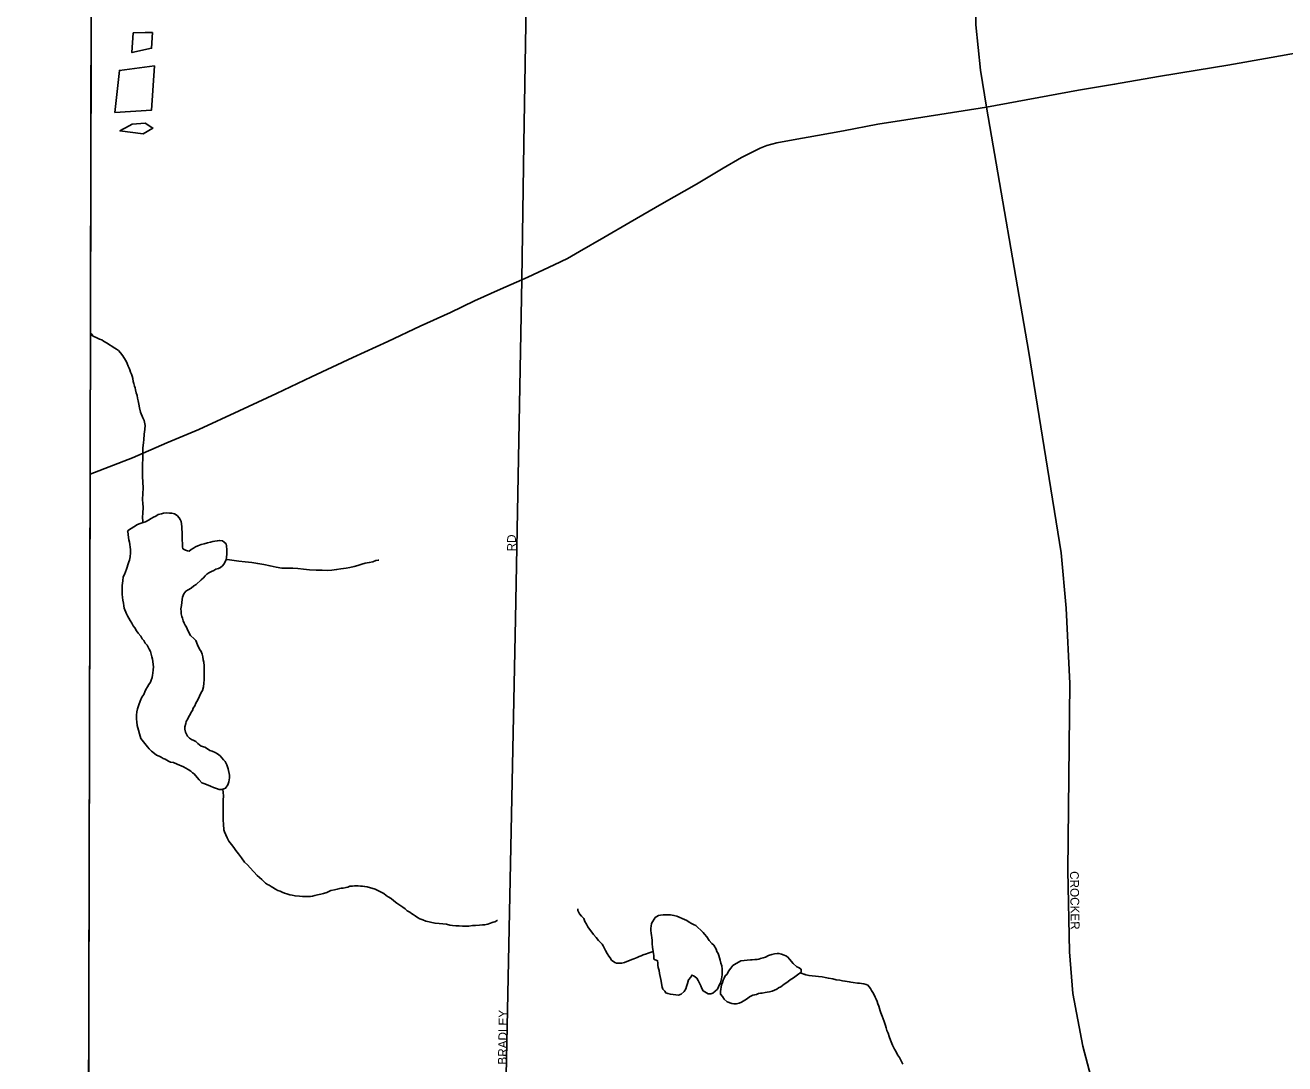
# Model space of a CAD drawing. Extents: x 2010165 to 2382125, y 1060529 to 1407316.
# Drawn here: x 2113583 to 2120777, y 1256857 to 1262787 of the extents above; entities that cross this region are included whole.
import ezdxf

# ---------------------------------------------------------------- set-up
doc = ezdxf.new("R2010")
doc.units = 0
for name, color, linetype in [('GM_X_Adjacent_County', 7, 'Continuous'), ('GM_X_City_Street', 7, 'Continuous'), ('GM_X_City_Street_Text', 7, 'Continuous'), ('GM_X_Corporation', 7, 'Continuous'), ('GM_X_County', 7, 'Continuous'), ('GM_X_Minor_Lake', 7, 'Continuous'), ('GM_X_Minor_River', 7, 'Continuous'), ('GM_X_State_Route', 7, 'Continuous')]:
    doc.layers.add(name, color=color, linetype=linetype)

msp = doc.modelspace()

# ---------------------------------------------------------------- linework, layer by layer
at = {"layer": 'GM_X_Adjacent_County'}
msp.add_lwpolyline([(2113401.8, 1277801), (2113713.6, 1277682.4), (2113866.9, 1277540.8), (2113869.4, 1277446.4), (2113925.9, 1277406.6), (2114036.3, 1277407.2), (2114028.2, 1277067.2), (2113991.2, 1275520.7), (2113984.5, 1272833.3), (2113971.4, 1267533.5), (2113963, 1264130), (2113962.6, 1263937.9), (2113955.8, 1261185.2), (2113953.5, 1260222.9), (2113939.6, 1254280.1)], dxfattribs=at)
at = {"layer": 'GM_X_City_Street'}
for points in [[(2116420.1, 1261333.2), (2116431.7, 1262110.4), (2116460.7, 1263925.9), (2116456.3, 1264106.2), (2116464.5, 1267466.7), (2116464.5, 1267467)], [(2119072.7, 1262319.5), (2119038.5, 1262529.6), (2119013, 1262787.9), (2119015.7, 1263206.7), (2119022.2, 1263344.1), (2119023.7, 1263364.7), (2119049.2, 1263720.7), (2119057.1, 1263831.3)], [(2119855.9, 1256226.1), (2119721.3, 1256589.9), (2119623.7, 1256958.7), (2119565.9, 1257258.7), (2119547.8, 1257497.4), (2119537.9, 1257961.4), (2119549.6, 1259029.2), (2119527.9, 1259459.4), (2119499, 1259773.9), (2119314.7, 1260918.5), (2119072.7, 1262319.5)], [(2116261.5, 1253143.9), (2116283.7, 1254169.9), (2116295.7, 1255116.1), (2116384, 1259397), (2116420.1, 1261333.2)]]:
    msp.add_lwpolyline(points, dxfattribs=at)
at = {"layer": 'GM_X_Corporation'}
msp.add_lwpolyline([(2087103.1, 1267526.8), (2100292, 1267571.3), (2105566.3, 1267515.2), (2113972.1, 1267511.1), (2113971.4, 1267404), (2113929.8, 1250070.4), (2113906.2, 1245908.9), (2107567, 1245842.9), (2100580.4, 1245842), (2087018.7, 1245699)], close=True, dxfattribs=at)
msp.add_lwpolyline([(2113929.8, 1250070.4), (2113971.4, 1267404), (2121968.1, 1267337), (2140205.4, 1267168.3), (2140069, 1257837), (2140063.6, 1257468.8), (2140046.9, 1256760.6)], dxfattribs=at)
at = {"layer": 'GM_X_County'}
msp.add_lwpolyline([(2113939.6, 1254280.1), (2113953.5, 1260222.9), (2113955.8, 1261185.2), (2113962.6, 1263937.9), (2113963, 1264130), (2113971.4, 1267533.5)], dxfattribs=at)
at = {"layer": 'GM_X_Minor_Lake'}
for points in [[(2114267.4, 1262744.5), (2114200.6, 1262742.9), (2114193, 1262630.5), (2114305.2, 1262655), (2114311, 1262745.6)], [(2114311, 1262745.6), (2114267.4, 1262744.5)], [(2114235, 1262543.2), (2114121.1, 1262528), (2114095.8, 1262289.1), (2114304.5, 1262301.8), (2114321.6, 1262554.7)], [(2114321.6, 1262554.7), (2114235, 1262543.2)], [(2114176.6, 1262211.5), (2114124.3, 1262182.8), (2114256.8, 1262167.2), (2114312.8, 1262199.5), (2114268.6, 1262227.4)], [(2114194.4, 1262221.2), (2114176.6, 1262211.5)], [(2114268.6, 1262227.4), (2114194.4, 1262221.2)], [(2114166.6, 1259899.8), (2114224.4, 1259935.7), (2114214.4, 1259929.7), (2114224.4, 1259935.7), (2114240.4, 1259941.8), (2114256.5, 1259947.8), (2114270.5, 1259951.9), (2114286.5, 1259960), (2114302.5, 1259970.1), (2114316.6, 1259978.1), (2114328.6, 1259984.2), (2114342.6, 1259992.3), (2114360.7, 1259996.3), (2114372.7, 1260000.4), (2114388.7, 1260002.4), (2114406.8, 1260000.5), (2114420.8, 1260000.6), (2114434.9, 1259996.6), (2114451, 1259986.6), (2114463.1, 1259974.6), (2114469.1, 1259964.6), (2114473.2, 1259952.6), (2114475.2, 1259940.5), (2114477.3, 1259922.5), (2114477.3, 1259908.4), (2114479.4, 1259894.4), (2114479.5, 1259880.3), (2114479.5, 1259866.3), (2114479.5, 1259854.2), (2114479.6, 1259842.2), (2114481.6, 1259832.2), (2114481.7, 1259822.1), (2114481.7, 1259808.1), (2114483.8, 1259798.1), (2114497.8, 1259790.1), (2114509.9, 1259786.1), (2114519.9, 1259784.1), (2114531.9, 1259794.2), (2114543.9, 1259800.3), (2114556, 1259808.3), (2114570, 1259814.4), (2114588, 1259822.5), (2114606.1, 1259826.6), (2114624.1, 1259830.6), (2114642.2, 1259834.7), (2114654.2, 1259838.8), (2114666.2, 1259840.8), (2114680.3, 1259842.8), (2114692.3, 1259844.9), (2114710.4, 1259842.9), (2114720.4, 1259834.9), (2114730.5, 1259824.9), (2114732.5, 1259812.9), (2114734.6, 1259792.8), (2114734.6, 1259780.8), (2114734.7, 1259768.8), (2114732.8, 1259748.7), (2114730.8, 1259736.6), (2114726.8, 1259726.6), (2114716.8, 1259710.5), (2114710.8, 1259700.5), (2114698.8, 1259690.4), (2114686.8, 1259684.3), (2114672.8, 1259680.3), (2114660.8, 1259674.2), (2114646.8, 1259668.1), (2114632.7, 1259660.1), (2114620.7, 1259652), (2114610.7, 1259644), (2114600.7, 1259631.9), (2114588.7, 1259619.8), (2114558.7, 1259593.6), (2114546.7, 1259585.6), (2114530.7, 1259573.5), (2114514.7, 1259563.4), (2114500.7, 1259555.3), (2114488.7, 1259541.2), (2114484.7, 1259531.2), (2114480.7, 1259521.1), (2114478.7, 1259507.1), (2114474.9, 1259473), (2114472.9, 1259454.9), (2114473, 1259438.8), (2114473, 1259426.8), (2114477.1, 1259410.8), (2114481.1, 1259400.7), (2114485.2, 1259386.7), (2114491.3, 1259372.7), (2114497.3, 1259360.7), (2114503.4, 1259350.6), (2114511.5, 1259330.6), (2114527.6, 1259302.6), (2114547.8, 1259282.6), (2114557.8, 1259274.6), (2114567.9, 1259248.5), (2114578.1, 1259224.5), (2114588.1, 1259210.4), (2114594.2, 1259196.4), (2114598.3, 1259180.4), (2114600.4, 1259164.3), (2114602.4, 1259150.3)], [(2114309.7, 1259075.1), (2114311.7, 1259087.2), (2114313.6, 1259107.2), (2114315.5, 1259123.3), (2114313.5, 1259137.3), (2114311.4, 1259153.4), (2114309.4, 1259167.4), (2114307.3, 1259181.5), (2114303.2, 1259195.5), (2114299.2, 1259211.5), (2114291.1, 1259223.6), (2114285.1, 1259235.6), (2114279, 1259247.6), (2114268.9, 1259259.6), (2114260.8, 1259273.6), (2114250.8, 1259283.6), (2114242.7, 1259299.6), (2114228.6, 1259315.6), (2114218.5, 1259329.7), (2114208.4, 1259345.7), (2114200.3, 1259357.7), (2114192.3, 1259373.7), (2114182.2, 1259387.8), (2114174.1, 1259401.8), (2114168, 1259413.8), (2114162, 1259425.8), (2114147.8, 1259457.9), (2114145.8, 1259471.9), (2114143.7, 1259488), (2114141.6, 1259504), (2114139.6, 1259520.1), (2114137.5, 1259538.1), (2114137.4, 1259554.2), (2114137.4, 1259572.2), (2114137.3, 1259588.3), (2114139.3, 1259600.3), (2114141.2, 1259614.4), (2114143.2, 1259636.5), (2114151.2, 1259650.5), (2114155.1, 1259666.6), (2114161.1, 1259680.7), (2114165.1, 1259692.7), (2114169, 1259706.8), (2114175, 1259722.8), (2114179, 1259732.9), (2114182.9, 1259751), (2114184.8, 1259775.1), (2114184.8, 1259793.1), (2114182.7, 1259807.1), (2114180.7, 1259821.2), (2114178.6, 1259835.2), (2114174.5, 1259849.3), (2114172.5, 1259861.3), (2114170.4, 1259879.4), (2114168.4, 1259895.4), (2114166.6, 1259899.8)], [(2114602.4, 1259150.3), (2114604.5, 1259130.2), (2114604.6, 1259102.1), (2114604.7, 1259074), (2114604.8, 1259050), (2114602.8, 1259029.9), (2114600.9, 1259009.8), (2114594.9, 1258987.7), (2114589, 1258977.7), (2114569, 1258935.5), (2114557.1, 1258915.4), (2114551.1, 1258901.3), (2114543.1, 1258887.2), (2114539.1, 1258875.2), (2114531.2, 1258865.1), (2114527.2, 1258855.1), (2114515.2, 1258837), (2114511.2, 1258826.9), (2114503.3, 1258810.8), (2114501.3, 1258800.8), (2114495.3, 1258780.7), (2114495.4, 1258768.7), (2114499.4, 1258750.6), (2114503.5, 1258738.6), (2114509.6, 1258728.6), (2114521.6, 1258716.6), (2114533.7, 1258708.6), (2114545.8, 1258702.6), (2114557.8, 1258696.6), (2114569.9, 1258686.6), (2114588, 1258670.6), (2114608.1, 1258664.7), (2114624.2, 1258654.7), (2114638.3, 1258646.7), (2114650.3, 1258642.7), (2114668.4, 1258634.8), (2114680.5, 1258626.8), (2114696.6, 1258614.8), (2114714.7, 1258592.8), (2114724.8, 1258582.8), (2114734.9, 1258564.8), (2114738.9, 1258552.7), (2114743, 1258540.7), (2114749.1, 1258504.6), (2114749.2, 1258490.5), (2114745.3, 1258466.4), (2114741.3, 1258450.4), (2114727.3, 1258430.3), (2114717.3, 1258426.2), (2114703.3, 1258424.2), (2114691.2, 1258424.1), (2114675.2, 1258428.1), (2114659.1, 1258434.1), (2114641, 1258442), (2114618.9, 1258452), (2114602.8, 1258458), (2114592.8, 1258461.9), (2114576.7, 1258477.9), (2114564.6, 1258492), (2114548.5, 1258512), (2114538.4, 1258518), (2114528.3, 1258528), (2114514.2, 1258537.9), (2114488.1, 1258551.9), (2114451.9, 1258567.9), (2114429.8, 1258577.8), (2114413.8, 1258579.8), (2114401.7, 1258585.8), (2114391.7, 1258591.7), (2114381.6, 1258595.7), (2114371.6, 1258599.7), (2114359.5, 1258607.7), (2114347.4, 1258613.7), (2114333.4, 1258619.7), (2114321.3, 1258629.7), (2114305.2, 1258641.6), (2114291.1, 1258655.6), (2114281, 1258667.6), (2114242.7, 1258713.7), (2114222.2, 1258788.2)], [(2114222.2, 1258788.2), (2114220.3, 1258809.9), (2114218.3, 1258824), (2114218.2, 1258836), (2114218.2, 1258848.1), (2114220.1, 1258866.1), (2114224.1, 1258884.2), (2114232, 1258906.3), (2114240, 1258928.4), (2114249.9, 1258950.5), (2114259.9, 1258966.6), (2114265.9, 1258980.7), (2114271.8, 1258994.7), (2114281.8, 1259008.8), (2114289.8, 1259022.9), (2114297.8, 1259036.9), (2114301.8, 1259047), (2114307.7, 1259063.1), (2114309.7, 1259075.1)], [(2117172.8, 1257455.3), (2117172.7, 1257475.4), (2117168.6, 1257499.4), (2117166.5, 1257523.5), (2117164.5, 1257541.6), (2117164.4, 1257561.6), (2117162.3, 1257577.7), (2117160.3, 1257589.7), (2117158.2, 1257603.8), (2117156.2, 1257617.8), (2117156.1, 1257631.8), (2117158.1, 1257643.9), (2117160, 1257657.9), (2117180, 1257692.1), (2117200, 1257704.2), (2117212, 1257706.3), (2117226.1, 1257708.3), (2117238.1, 1257708.4), (2117252.2, 1257708.4), (2117268.2, 1257708.5), (2117288.3, 1257704.5), (2117304.4, 1257700.6), (2117318.4, 1257694.6), (2117334.5, 1257686.6), (2117348.6, 1257680.6), (2117362.7, 1257674.6), (2117374.7, 1257666.7), (2117388.8, 1257658.7), (2117402.9, 1257650.7), (2117412.9, 1257646.7), (2117452.7, 1257609.5)], [(2117452.7, 1257609.5), (2117455.2, 1257606.7), (2117463.3, 1257596.7), (2117475.4, 1257582.7), (2117489.5, 1257560.7), (2117503.6, 1257544.6), (2117515.6, 1257534.6), (2117529.8, 1257512.6), (2117533.8, 1257498.6), (2117539.9, 1257486.6), (2117543.9, 1257476.6), (2117548, 1257462.5), (2117552.1, 1257448.5), (2117556.1, 1257432.4), (2117562.2, 1257416.4), (2117564.3, 1257398.3), (2117564.3, 1257386.3), (2117564.4, 1257366.2), (2117560.5, 1257342.1), (2117554.5, 1257320.1), (2117546.6, 1257306), (2117542.6, 1257295.9), (2117536.6, 1257283.9), (2117510.6, 1257259.7), (2117498.6, 1257257.7), (2117484.5, 1257257.6), (2117474.5, 1257261.6), (2117464.4, 1257267.6), (2117454.4, 1257273.6), (2117448.3, 1257287.6), (2117442.2, 1257301.6), (2117434.1, 1257317.7), (2117426.1, 1257333.7), (2117418, 1257345.7), (2117403.9, 1257357.7), (2117389.8, 1257363.7), (2117383.9, 1257351.6), (2117371.9, 1257337.5), (2117365.9, 1257315.4), (2117360, 1257299.4), (2117356, 1257285.3), (2117346, 1257269.2), (2117330, 1257255.1), (2117314, 1257249.1), (2117299.9, 1257251), (2117283.9, 1257253), (2117267.8, 1257254.9), (2117253.7, 1257258.9), (2117241.7, 1257262.9), (2117235.6, 1257272.9), (2117225.6, 1257282.9), (2117221.5, 1257294.9), (2117213.3, 1257339), (2117209.3, 1257355.1), (2117205.2, 1257373.1), (2117203.1, 1257389.2), (2117199, 1257407.2), (2117197, 1257421.3), (2117196.9, 1257433.3), (2117194.9, 1257445.3), (2117172.8, 1257455.3)], [(2117725.1, 1257450.4), (2117734.8, 1257450.5), (2117750.8, 1257452.5), (2117762.9, 1257452.6), (2117772.9, 1257454.6), (2117782.9, 1257458.7), (2117797, 1257462.7), (2117811, 1257466.8), (2117829, 1257474.9), (2117847.1, 1257480.9), (2117863.1, 1257485), (2117877.1, 1257487.1), (2117887.2, 1257487.1), (2117903.2, 1257483.1), (2117917.3, 1257477.1), (2117927.4, 1257473.2), (2117937.4, 1257467.2), (2117949.5, 1257453.2), (2117957.6, 1257443.2), (2117969.7, 1257429.1), (2117989.8, 1257411.1), (2117999.8, 1257407.2), (2118013.9, 1257397.2), (2118014, 1257381.1), (2117994, 1257365), (2117971.9, 1257348.9), (2117951.9, 1257336.8), (2117939.9, 1257326.7), (2117927.9, 1257318.6), (2117917.9, 1257312.6), (2117897.9, 1257296.5), (2117885.9, 1257290.4), (2117875.8, 1257284.4), (2117861.8, 1257278.3), (2117849.8, 1257272.2), (2117833.8, 1257268.2), (2117819.7, 1257266.1), (2117809.7, 1257264.1), (2117791.6, 1257260), (2117781.6, 1257260), (2117771.6, 1257257.9), (2117759.6, 1257253.9), (2117749.5, 1257251.9), (2117739.5, 1257249.8), (2117719.5, 1257239.7), (2117707.5, 1257229.6), (2117693.5, 1257221.6), (2117683.4, 1257215.5), (2117673.4, 1257209.5), (2117661.4, 1257203.4), (2117645.4, 1257199.3), (2117631.3, 1257199.3), (2117619.3, 1257201.3), (2117591.2, 1257211.2), (2117575, 1257227.2), (2117565, 1257241.2), (2117554.9, 1257255.2), (2117554.8, 1257269.3), (2117556.8, 1257283.3), (2117558.8, 1257295.4), (2117560.7, 1257307.4), (2117564.7, 1257321.5), (2117568.6, 1257335.6), (2117574.6, 1257345.6), (2117580.6, 1257359.7), (2117592.6, 1257369.8), (2117600.6, 1257385.8), (2117612.6, 1257403.9), (2117624.5, 1257418), (2117634.6, 1257424.1)], [(2117634.6, 1257424.1), (2117670.6, 1257444.3), (2117725.1, 1257450.4)]]:
    msp.add_lwpolyline(points, dxfattribs=at)
at = {"layer": 'GM_X_Minor_River'}
for points in [[(2113959.6, 1261026.5), (2113971.8, 1261010.5), (2113957.8, 1261020.5), (2113971.8, 1261010.5), (2113991.9, 1261002.5), (2114008, 1260994.5), (2114020.1, 1260990.6), (2114030.1, 1260982.6), (2114048.2, 1260972.6), (2114094.5, 1260942.6), (2114104.5, 1260936.7), (2114116.6, 1260928.7), (2114126.7, 1260916.7), (2114140.8, 1260898.6), (2114146.8, 1260888.6), (2114158.9, 1260868.6), (2114165, 1260854.6), (2114171.1, 1260840.6), (2114177.1, 1260828.5), (2114181.2, 1260818.5), (2114185.2, 1260806.5), (2114189.3, 1260794.4), (2114193.4, 1260782.4), (2114197.4, 1260770.4), (2114199.5, 1260752.3), (2114203.5, 1260740.3), (2114207.6, 1260726.3), (2114211.7, 1260716.3), (2114213.7, 1260704.2), (2114217.8, 1260688.2), (2114221.8, 1260672.1), (2114223.9, 1260658.1), (2114228, 1260642.1), (2114232, 1260624), (2114236.1, 1260602), (2114242.2, 1260577.9), (2114254.4, 1260545.8), (2114262.5, 1260529.8), (2114268.6, 1260501.7), (2114266.7, 1260479.6), (2114264.7, 1260463.6), (2114262.7, 1260453.6), (2114262.8, 1260441.5), (2114260.8, 1260429.5), (2114260.8, 1260419.4), (2114258.9, 1260403.4), (2114256.9, 1260387.3), (2114255, 1260373.3), (2114255, 1260361.2), (2114255.1, 1260329.1), (2114255.2, 1260301), (2114253.3, 1260291), (2114253.3, 1260278.9), (2114253.3, 1260268.9), (2114253.4, 1260258.9), (2114253.4, 1260246.8), (2114253.5, 1260236.8), (2114253.5, 1260226.8), (2114253.5, 1260216.7), (2114253.6, 1260200.7), (2114255.6, 1260186.6), (2114255.7, 1260168.6), (2114257.8, 1260154.6), (2114257.8, 1260136.5), (2114255.9, 1260120.4), (2114255.9, 1260102.4), (2114254, 1260090.3), (2114254, 1260074.3), (2114254.1, 1260060.2), (2114254.1, 1260050.2), (2114256.2, 1260040.2), (2114256.2, 1260022.1), (2114254.2, 1260012.1), (2114254.3, 1259996), (2114252.3, 1259984), (2114254.2, 1259947)], [(2114736.8, 1259736.7), (2114803.1, 1259726.8), (2114736.8, 1259736.7), (2114803.1, 1259726.8), (2114839.2, 1259722.9), (2114877.3, 1259719.1), (2114911.5, 1259713.1), (2114945.6, 1259707.2), (2114981.8, 1259699.3), (2115015.9, 1259693.4), (2115048, 1259687.5), (2115084.1, 1259687.6), (2115112.2, 1259687.7), (2115140.3, 1259685.8), (2115172.5, 1259681.9), (2115206.6, 1259678), (2115244.7, 1259676.1), (2115278.8, 1259676.2), (2115306.9, 1259674.3), (2115335, 1259676.4), (2115361.1, 1259678.5), (2115385.2, 1259682.6), (2115415.3, 1259686.6), (2115437.3, 1259690.7), (2115461.4, 1259696.8), (2115483.4, 1259702.9), (2115505.5, 1259709), (2115525.5, 1259715.1), (2115547.6, 1259719.2), (2115567.6, 1259723.3), (2115585.7, 1259731.3), (2115599.7, 1259733.4), (2115601.7, 1259733.4), (2115603.7, 1259733.4)], [(2114711.3, 1258425.3), (2114715.4, 1258388.1), (2114713.5, 1258362), (2114713.6, 1258339.9), (2114713.7, 1258323.9), (2114713.7, 1258305.8), (2114713.8, 1258287.8), (2114713.8, 1258271.7), (2114713.9, 1258255.6), (2114713.9, 1258243.6), (2114716, 1258229.6), (2114716, 1258215.5), (2114718.1, 1258203.5), (2114718.1, 1258193.4), (2114722.2, 1258181.4), (2114728.3, 1258165.4), (2114736.4, 1258147.3), (2114746.4, 1258129.3), (2114760.6, 1258109.3), (2114774.7, 1258091.3), (2114786.8, 1258075.3), (2114800.9, 1258055.2), (2114819, 1258033.2), (2114835.2, 1258009.2), (2114853.3, 1257993.2), (2114867.4, 1257975.2), (2114907.7, 1257933.2), (2114921.8, 1257921.2), (2114933.8, 1257909.2), (2114943.9, 1257899.2), (2114956, 1257889.2), (2114966, 1257881.2), (2114976.1, 1257877.2), (2114988.2, 1257869.2), (2114998.2, 1257863.2), (2115012.3, 1257855.2), (2115026.4, 1257847.2), (2115038.4, 1257843.3), (2115050.5, 1257837.3), (2115064.5, 1257831.3), (2115076.6, 1257827.3), (2115094.7, 1257821.4), (2115108.7, 1257819.4), (2115124.8, 1257815.5), (2115148.9, 1257813.5), (2115167, 1257811.6), (2115183, 1257811.6), (2115199.1, 1257811.7), (2115211.1, 1257811.7), (2115223.1, 1257813.8), (2115237.2, 1257817.8), (2115253.2, 1257821.9), (2115271.3, 1257825.9), (2115287.3, 1257830), (2115305.3, 1257836.1), (2115329.4, 1257846.2), (2115349.4, 1257850.3), (2115365.5, 1257854.3), (2115379.5, 1257858.4), (2115389.5, 1257860.4), (2115399.6, 1257860.5), (2115415.6, 1257864.6), (2115425.6, 1257866.6), (2115437.7, 1257870.6), (2115451.7, 1257870.7), (2115463.7, 1257872.7), (2115483.8, 1257872.8), (2115497.9, 1257870.8), (2115509.9, 1257870.9), (2115521.9, 1257868.9), (2115536, 1257866.9), (2115582.2, 1257855), (2115600.3, 1257845.1), (2115616.4, 1257837.1), (2115630.4, 1257829.1), (2115644.5, 1257819.1), (2115656.6, 1257811.1), (2115672.7, 1257801.1), (2115688.8, 1257787.1), (2115704.9, 1257775.2), (2115723, 1257763.2), (2115739.1, 1257751.2), (2115753.2, 1257741.2), (2115765.2, 1257731.2), (2115779.3, 1257723.2), (2115789.4, 1257715.2), (2115799.4, 1257709.2), (2115809.5, 1257701.2), (2115823.6, 1257693.3), (2115837.6, 1257685.3), (2115853.7, 1257679.3), (2115871.8, 1257671.3), (2115889.9, 1257667.4), (2115905.9, 1257663.4), (2115924, 1257659.5), (2115948.1, 1257657.5), (2115968.2, 1257655.6), (2115988.3, 1257653.6)], [(2116738.5, 1257742.3), (2116738.5, 1257732.3), (2116748.6, 1257714.3), (2116760.7, 1257700.2), (2116772.8, 1257686.2), (2116778.8, 1257670.2), (2116788.9, 1257654.2), (2116797, 1257640.1), (2116829.3, 1257596.1), (2116843.4, 1257578.1), (2116857.5, 1257562.1), (2116869.6, 1257550.1), (2116877.6, 1257540.1), (2116883.7, 1257530.1), (2116889.7, 1257520), (2116897.8, 1257504), (2116905.9, 1257488), (2116916, 1257472), (2116924.1, 1257461.9), (2116932.1, 1257449.9), (2116950.2, 1257435.9), (2116960.3, 1257432), (2116980.3, 1257432), (2116990.4, 1257432.1), (2117006.4, 1257436.1), (2117018.4, 1257442.2), (2117034.5, 1257446.3), (2117048.5, 1257452.3), (2117058.5, 1257456.4), (2117068.5, 1257460.4), (2117078.6, 1257464.4), (2117088.6, 1257470.5), (2117100.6, 1257474.6), (2117112.6, 1257478.6), (2117130.7, 1257484.7), (2117140.7, 1257488.7), (2117168.6, 1257499.4)], [(2115988.3, 1257653.6), (2116008.3, 1257649.7), (2116024.4, 1257647.7), (2116042.5, 1257645.8), (2116062.5, 1257645.8), (2116080.6, 1257643.9), (2116100.7, 1257644), (2116116.7, 1257644), (2116136.8, 1257646.1), (2116154.8, 1257646.1), (2116176.9, 1257648.2), (2116195, 1257650.3), (2116207, 1257650.3), (2116225, 1257654.4), (2116235.1, 1257658.4), (2116255.1, 1257666.5), (2116265.1, 1257668.6), (2116279.2, 1257674.6), (2116281.2, 1257674.6)], [(2118037.8, 1257366.4), (2118042.1, 1257365.2), (2118008.3, 1257376.6)], [(2118031.4, 1257368.2), (2118042.1, 1257365.2), (2118060.2, 1257361.2), (2118078.3, 1257359.2), (2118096.3, 1257357.3), (2118114.4, 1257355.4), (2118134.5, 1257353.4), (2118152.5, 1257349.5), (2118170.6, 1257345.5), (2118194.7, 1257341.6), (2118214.8, 1257337.6), (2118234.9, 1257335.7), (2118250.9, 1257331.7), (2118265, 1257329.8), (2118277, 1257327.8), (2118289.1, 1257325.8), (2118299.1, 1257323.8), (2118311.2, 1257321.9), (2118337.3, 1257317.9), (2118347.3, 1257318), (2118359.3, 1257316), (2118373.4, 1257314), (2118385.5, 1257310.1), (2118395.5, 1257306.1), (2118411.6, 1257288.1), (2118415.7, 1257276.1), (2118423.7, 1257264), (2118429.8, 1257254), (2118437.9, 1257238), (2118443.9, 1257226), (2118448, 1257213.9), (2118452.1, 1257199.9), (2118458.1, 1257185.9), (2118462.2, 1257173.8), (2118466.3, 1257159.8), (2118470.3, 1257147.8), (2118476.4, 1257129.7), (2118482.5, 1257113.7), (2118488.5, 1257099.7), (2118492.6, 1257087.6), (2118496.7, 1257075.6), (2118500.7, 1257063.6), (2118504.8, 1257047.6), (2118510.9, 1257031.5), (2118516.9, 1257013.5), (2118525, 1256991.4), (2118537.2, 1256963.4), (2118547.3, 1256941.3), (2118557.4, 1256925.3), (2118565.5, 1256909.3), (2118575.6, 1256893.3), (2118585.6, 1256875.2), (2118595.8, 1256855.2)]]:
    msp.add_lwpolyline(points, dxfattribs=at)
at = {"layer": 'GM_X_State_Route'}
msp.add_lwpolyline([(2113953.5, 1260222.9), (2114195.4, 1260316), (2114391.7, 1260402.1), (2114574.1, 1260478.2), (2114804.4, 1260584.4), (2115018.8, 1260684.6), (2115219.1, 1260778.7), (2115453.5, 1260888.9), (2115653.9, 1260981), (2115838.2, 1261069.2), (2116012.5, 1261147.3), (2116148.7, 1261213.4), (2116297, 1261279.5), (2116420.1, 1261333.2), (2116453.2, 1261347.6), (2116603.5, 1261417.8), (2116679.6, 1261453.8), (2116749.7, 1261493.9), (2116888, 1261574.1), (2117038.3, 1261662.2), (2117218.6, 1261766.4), (2117416.9, 1261878.6), (2117569.2, 1261970.7), (2117673.3, 1262030.8), (2117735.4, 1262060.9), (2117781.5, 1262084.9), (2117819.6, 1262099), (2117875.7, 1262115), (2117969.8, 1262133), (2118108.1, 1262157), (2118256.3, 1262183), (2118452.6, 1262221.1), (2118612.9, 1262247.1), (2119072.7, 1262319.5), (2119598.5, 1262415.2), (2119804.9, 1262449.2), (2120055.3, 1262493.2), (2120275.6, 1262529.2), (2120451.9, 1262559.3), (2120698.4, 1262601.3), (2120964.8, 1262649.3)], dxfattribs=at)

# ---------------------------------------------------------------- texts
at = {"layer": 'GM_X_City_Street_Text'}
for s, rotation, p in [('RD', 90, (2116385.6, 1259782.7)), ('CROCKER', 270.86761, (2119549.8, 1257956.9)), ('BRADLEY', 89.13244, (2116332.8, 1256852.5))]:
    msp.add_text(s, height=50, rotation=rotation, dxfattribs=at).set_placement(p)

doc.saveas('drawing.dxf')
